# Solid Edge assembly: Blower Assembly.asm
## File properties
Author: CADCIM
Template: NORMENG.ASM
Last saved by: TIET
Revision: 12
Application: Solid Edge
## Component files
Lower Housing.par
upper housing.par
Blower.par
cover.par
motorshaft.par
Motor.par
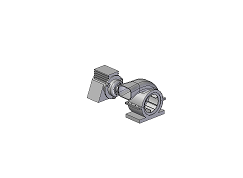
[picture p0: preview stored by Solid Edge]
